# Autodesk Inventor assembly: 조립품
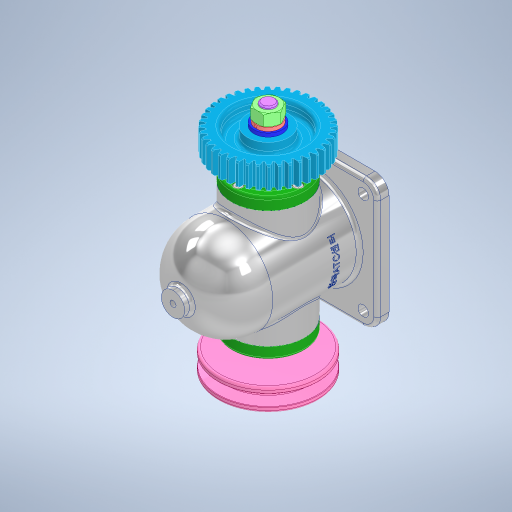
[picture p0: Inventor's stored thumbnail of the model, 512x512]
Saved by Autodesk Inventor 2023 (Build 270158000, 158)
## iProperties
Created: 2025-04
Part Number: 조립품
Document SubType Name: Assembly
Designer: ADMIN_PC
Author: ADMIN_PC
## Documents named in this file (14)
- C:\Users\ADMIN_PC\Desktop\750406V1008\조립품.iam
- C:\Users\ADMIN_PC\Desktop\750406V1008\본체.ipt
- C:\Users\ADMIN_PC\Desktop\750406V1008\깊은 홈 볼 베어링 6203.ipt
- C:\Users\ADMIN_PC\Desktop\750406V1008\축.ipt
- C:\Users\ADMIN_PC\Desktop\750406V1008\커버.ipt
- C:\Users\ADMIN_PC\Desktop\750406V1008\오일 실 26 38 8.ipt
- C:\Users\ADMIN_PC\Desktop\750406V1008\6각 구멍붙이 볼트 M4x12.ipt
- C:\Users\ADMIN_PC\Desktop\750406V1008\칼라.ipt
- C:\Users\ADMIN_PC\Desktop\750406V1008\평행 키 5x5x12.ipt
- C:\Users\ADMIN_PC\Desktop\750406V1008\스퍼기어.ipt
- C:\Users\ADMIN_PC\Desktop\750406V1008\V 벨트 풀리.ipt
- C:\Users\ADMIN_PC\Desktop\750406V1008\평와셔 M12.ipt
- C:\Users\ADMIN_PC\Desktop\750406V1008\스프링 와셔 M12.ipt
- C:\Users\ADMIN_PC\Desktop\750406V1008\6각 너트 M12x1.ipt
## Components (11 placed, 3 different names)
1. 6각 구멍붙이 볼트 M4x12:1
2. 6각 구멍붙이 볼트 M4x12:2
3. 6각 구멍붙이 볼트 M4x12:3
4. 6각 구멍붙이 볼트 M4x12:4
5. 6각 구멍붙이 볼트 M4x12:5
6. 6각 구멍붙이 볼트 M4x12:6
7. 6각 구멍붙이 볼트 M4x12:7
8. 6각 구멍붙이 볼트 M4x12:8
9. V 벨트 풀리:1
10. 6각 너트 M12x1:1
11. 6각 너트 M12x1:2
